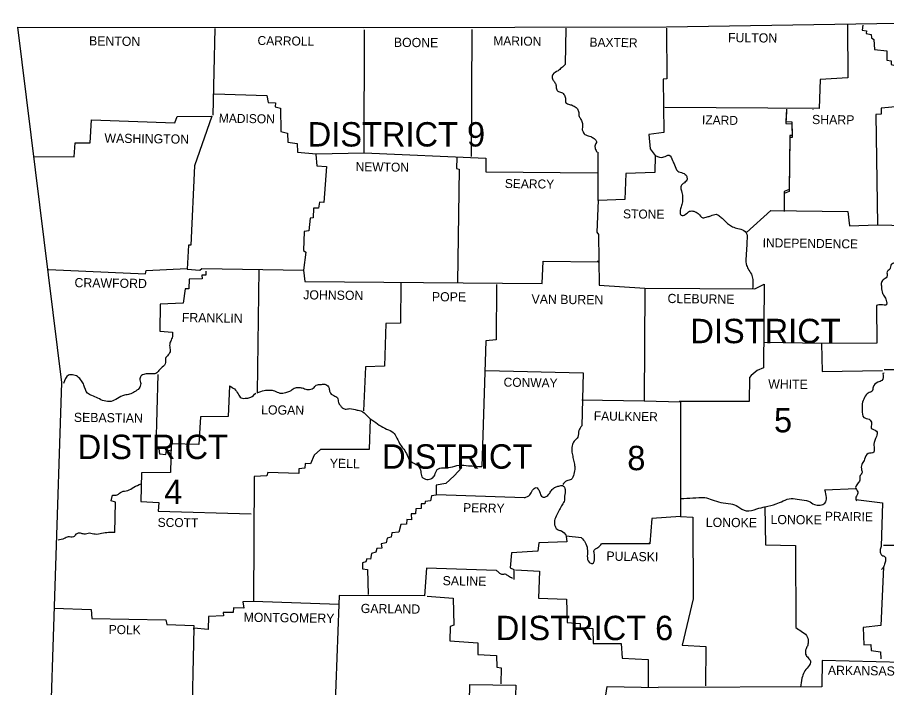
# Model space of a CAD drawing. Extents: x 185 to 5012, y 113 to 2127.
# Drawn here: x 4330.9 to 4728.7, y 1654.2 to 1960.9 of the extents above; entities that cross this region are included whole.
import ezdxf

# ---------------------------------------------------------------- set-up
doc = ezdxf.new("R2010")
doc.units = 0
for name, color, linetype in [('1', 7, 'Continuous'), ('2', 7, 'Continuous'), ('3', 7, 'Continuous')]:
    doc.layers.add(name, color=color, linetype=linetype)

msp = doc.modelspace()

# ---------------------------------------------------------------- linework, layer by layer
at = {"layer": '1'}
msp.add_line((4727.55, 1799.78), (4739.2, 1799.78), dxfattribs=at)
for points in [[(4330.91, 1956.42), (4489.12, 1956.32), (4627.95, 1956.61), (4791.74, 1959.16), (4867.66, 1960.92)], [(4710.82, 1957.49), (4711.02, 1933.23), (4698.3, 1932.55), (4697.91, 1919.24), (4627.17, 1919.63)], [(4717.87, 1957.4), (4717.57, 1955.05), (4719.53, 1954.76), (4719.43, 1953.58), (4721.68, 1953.09), (4721.88, 1951.53), (4722.95, 1950.84), (4723.25, 1946.15), (4728.83, 1945.56), (4728.83, 1941.35), (4730.88, 1941.06), (4730.88, 1939.39), (4732.64, 1938.9), (4732.54, 1933.23), (4734.11, 1932.94), (4734.5, 1920.12), (4726.18, 1919.34), (4726.28, 1916.6), (4723.74, 1916.5), (4724.62, 1866.01), (4764.05, 1865.13), (4764.73, 1786.66), (4739, 1785.98), (4738.51, 1799.19)], [(4330.91, 1956.42), (4351.16, 1793.81), (4342.35, 1528.37)], [(4421.21, 1955.83), (4420.33, 1916.21)], [(4421.02, 1925.89), (4445.09, 1925.11), (4445.67, 1921.98), (4449, 1921.88), (4448.9, 1919.92), (4451.25, 1919.34), (4451.45, 1908.67), (4454.48, 1907.99), (4454.68, 1903.78), (4458.98, 1903.19), (4459.18, 1899.28), (4467.69, 1898.4), (4489.6, 1898.89), (4489.8, 1955.15)], [(4538.82, 1955.34), (4538.52, 1897.22)], [(4581.87, 1956.03), (4581.67, 1939.3)], [(4627.95, 1956.03), (4628.15, 1932.74), (4626.48, 1932.64), (4626.78, 1908.28), (4619.93, 1907.3), (4620.52, 1900.75), (4622.86, 1897.71), (4622.67, 1889.98), (4609.36, 1889.5), (4608.87, 1877.56), (4596.74, 1877.17), (4596.15, 1862.69), (4596.84, 1861.51), (4597.13, 1838.42), (4618.07, 1837.05), (4617.78, 1785.49), (4634.41, 1785), (4634.41, 1732.56), (4621.3, 1731.58), (4620.32, 1720.04), (4598.31, 1719.94)], [(4682.84, 1918.95), (4682.64, 1913.27), (4685.38, 1913.07), (4685.48, 1906.81), (4684.5, 1906.81), (4684.11, 1882.16), (4681.86, 1881.18), (4681.86, 1872.96)], [(4682.84, 1918.06), (4682.64, 1912.39), (4685.38, 1912.19), (4685.48, 1905.93), (4684.5, 1905.93), (4684.11, 1881.28), (4681.86, 1880.3), (4681.86, 1872.08)], [(4695.07, 1918.75), (4695.17, 1918.85)], [(4338.64, 1897.22), (4356.93, 1897.13), (4357.42, 1903.58), (4364.17, 1903.58), (4364.76, 1914.05), (4402.92, 1912.68), (4404.09, 1915.62), (4419.84, 1915.72), (4411.92, 1893.02), (4410.35, 1856.72), (4409.18, 1856.62), (4408.59, 1845.66), (4414.37, 1845.17), (4415.25, 1846.05), (4461.92, 1845.17), (4462.4, 1839.99)], [(4467.49, 1898.2), (4467.88, 1892.92), (4472.38, 1892.63), (4471.21, 1876.19), (4469.16, 1876.29), (4468.76, 1873.65), (4466.42, 1873.65), (4466.32, 1869.14), (4464.85, 1869.05), (4464.36, 1863.27), (4462.21, 1862.98), (4461.92, 1854.17), (4462.89, 1853.49), (4461.92, 1845.17)], [(4489.6, 1898.89), (4545.37, 1896.54), (4545.28, 1890.18), (4596.45, 1889.79)], [(4596.74, 1877.17), (4596.64, 1899.18)], [(4531.97, 1896.83), (4531.87, 1891.75), (4533.14, 1891.45), (4532.36, 1839.79)], [(4664.64, 1862.49), (4675.8, 1872.57), (4711.02, 1872.08), (4711.7, 1865.52), (4724.52, 1866.01)], [(4345.09, 1845.56), (4389.61, 1843.51), (4389.81, 1845.08), (4408.4, 1845.96)], [(4462.4, 1839.99), (4571.01, 1839.11), (4571.5, 1849.38), (4596.74, 1849.09)], [(4596.45, 1849.19), (4596.74, 1849.48)], [(4417.2, 1844.78), (4417.2, 1843.02), (4415.34, 1843.02), (4415.44, 1841.26), (4409.47, 1841.16), (4409.38, 1836.76), (4407.71, 1836.76), (4406.83, 1830.2), (4396.26, 1829.71), (4396.17, 1817.29), (4401.84, 1816.9)], [(4441.37, 1845.56), (4440.68, 1789.11)], [(4506.34, 1839.21), (4506.24, 1820.91), (4499.49, 1820.81), (4498.9, 1801.34), (4490.29, 1801.05), (4489.31, 1780.89)], [(4550.17, 1838.72), (4549.97, 1813.28), (4545.28, 1812.89), (4543.42, 1755.36)], [(4618.07, 1837.05), (4668.36, 1836.76), (4672.66, 1838.81), (4672.37, 1800.56), (4669.44, 1799.29), (4666.79, 1797.04), (4665.91, 1796.16), (4665.82, 1785.2), (4633.82, 1785.2)], [(4724.13, 1829.03), (4724.32, 1811.81), (4698.89, 1811.71), (4672.76, 1812.2)], [(4698.89, 1811.71), (4699.28, 1798.89), (4726.77, 1799.38)], [(4545.08, 1799.29), (4589.79, 1798.21), (4589.21, 1774.04)], [(4395.19, 1797.53), (4394.21, 1763.87), (4395.68, 1763.48), (4395.97, 1761.13), (4398.91, 1760.93), (4399.2, 1762.6), (4401.55, 1762.99)], [(4727.55, 1798.11), (4727.06, 1798.01)], [(4428.06, 1792.24), (4427.38, 1778.25), (4414.66, 1778.15), (4413.97, 1765.43), (4401.35, 1765.73), (4400.96, 1752.62), (4387.75, 1752.52), (4387.36, 1739.41), (4395.68, 1738.92), (4395.38, 1734.91), (4437.85, 1733.73)], [(4764.73, 1786.66), (4766.2, 1733.05), (4742.91, 1732.95), (4742.82, 1730.8), (4736.07, 1730.41), (4735.48, 1719.25), (4727.26, 1719.25)], [(4589.3, 1785.88), (4617.78, 1785.49)], [(4492.34, 1777.27), (4491.95, 1763.18), (4469.65, 1763.09), (4466.71, 1760.54), (4465.05, 1756.63), (4462.6, 1756.82), (4462.5, 1754.57), (4459.67, 1754.28), (4459.76, 1752.22), (4445.58, 1752.62), (4445.09, 1751.05), (4439.22, 1750.86), (4439.02, 1693.62), (4434.13, 1693.52), (4434.52, 1690.59), (4429.82, 1690.68), (4429.73, 1688.53), (4425.13, 1688.53), (4425.23, 1686.97), (4418.38, 1686.77), (4418.28, 1680.8), (4411.63, 1681.39), (4410.55, 1633.25)], [(4534.32, 1754.96), (4530.8, 1751.15), (4526.98, 1747.53), (4522.58, 1746.84), (4522.58, 1742.25), (4520.42, 1741.95), (4520.03, 1739.6), (4517.59, 1739.41), (4517.39, 1738.33), (4515.73, 1738.23), (4515.63, 1736.18), (4513.28, 1736.08), (4513.09, 1733.73), (4511.13, 1733.73), (4511.23, 1730.99), (4509.07, 1731.19), (4508.98, 1729.04), (4506.34, 1728.84), (4505.55, 1725.32), (4502.23, 1725.03), (4501.93, 1723.07), (4500.17, 1722.58), (4499.68, 1720.52), (4497.43, 1720.04), (4497.63, 1717.98), (4495.38, 1717.78), (4494.99, 1716.22), (4492.93, 1715.63), (4492.44, 1712.99), (4490.88, 1713.09), (4490.39, 1711.72), (4488.92, 1711.23), (4488.82, 1708.59), (4491.07, 1708.2), (4491.46, 1696.85)], [(4700.45, 1744.69), (4714.64, 1745.38)], [(4375.52, 1725.22), (4375.82, 1739.02), (4373.86, 1739.6), (4374.45, 1742.25)], [(4562.99, 1741.07), (4522.67, 1742.34)], [(4714.64, 1740.29), (4726.87, 1738.72), (4726.18, 1718.76)], [(4673.06, 1737.06), (4673.25, 1719.55), (4687.05, 1719.25), (4687.14, 1681.68)], [(4634.41, 1732.56), (4640.08, 1732.17), (4640.18, 1694.79), (4635.09, 1673.56), (4645.95, 1673.07), (4645.86, 1655.07)], [(4589.11, 1722.77), (4582.06, 1723.56), (4582.36, 1720.92), (4569.54, 1720.43), (4569.15, 1716.61), (4557.11, 1715.93), (4556.43, 1709.08), (4558.19, 1708.2), (4558.19, 1703.7)], [(4619.83, 1720.13), (4620.32, 1720.62)], [(4550.17, 1707.81), (4518.17, 1708.78), (4517.29, 1696.16), (4478.16, 1696.36), (4477.96, 1692.15)], [(4558.88, 1708.1), (4569.83, 1707.41), (4569.44, 1695.18), (4582.26, 1694.69), (4582.46, 1684.03), (4588.52, 1683.54), (4588.52, 1681.68), (4594.2, 1681.29), (4594.39, 1674.44), (4607.31, 1674.44), (4607.7, 1667.69), (4619.63, 1667.1), (4619.54, 1654.38)], [(4727.26, 1709.37), (4726.09, 1682.56), (4718.06, 1681.68), (4718.26, 1673.76), (4721.49, 1673.85), (4721.58, 1671.11), (4725.99, 1670.63), (4726.09, 1667.4)], [(4518.47, 1695.97), (4530.31, 1695.09), (4530.7, 1682.76), (4529.03, 1682.17), (4528.84, 1675.62), (4541.66, 1674.74), (4541.66, 1669.35), (4550.17, 1668.86), (4550.27, 1663.48), (4552.32, 1663.19), (4552.22, 1655.95)], [(4477.96, 1692.15), (4439.02, 1693.62)], [(4477.96, 1692.15), (4475.71, 1631.2)], [(4347.74, 1690.59), (4364.66, 1690), (4365.05, 1685.89), (4398.91, 1685.2), (4399.3, 1683.05), (4411.63, 1682.66), (4411.53, 1680.8)], [(4736.26, 1665.64), (4699.28, 1666.61), (4699.08, 1654.58), (4624.23, 1654.29)], [(4476.4, 1639.32), (4532.36, 1638.53), (4533.44, 1647.83), (4537.84, 1647.83), (4537.94, 1655.66), (4559.07, 1655.36), (4558.88, 1650.67), (4564.35, 1650.27), (4564.35, 1641.66), (4567.88, 1641.37)], [(4567.88, 1641.37), (4573.36, 1642.15), (4573.75, 1645.48), (4576.98, 1646.07), (4577.17, 1648.02), (4599.97, 1648.71), (4600.85, 1654.68), (4624.23, 1654.29)]]:
    msp.add_lwpolyline(points, dxfattribs=at)
for points in [[(4581.67, 1939.3), (4579.91, 1937.83), (4578.35, 1936.46), (4576, 1934.8), (4575.7, 1933.23), (4576.49, 1931.66), (4577.27, 1930.39), (4577.56, 1928.63), (4578.25, 1927.16), (4579.91, 1926.58), (4581.28, 1925.31), (4581.77, 1923.54), (4581.97, 1921.88), (4583.53, 1921.1), (4585.29, 1920.51), (4586.96, 1919.34), (4587.74, 1917.87), (4587.93, 1916.01), (4588.62, 1914.54), (4589.4, 1912.78), (4589.6, 1911.31), (4589.4, 1909.85), (4589.79, 1908.48), (4591.07, 1907.11), (4593.32, 1906.42), (4594.88, 1905.44), (4595.96, 1904.07), (4595.27, 1902.41), (4595.37, 1900.94), (4596.25, 1899.18)], [(4622.86, 1897.71), (4626.78, 1897.03), (4629.13, 1897.91), (4630.79, 1895.37), (4631.67, 1893.41), (4633.14, 1890.57), (4635.49, 1889.69), (4637.25, 1888.13), (4637.25, 1886.46), (4635.68, 1884.9), (4634.51, 1883.33), (4634.9, 1881.47), (4635.29, 1878.93), (4635.29, 1876.48), (4634.7, 1874.23), (4634.21, 1872.18), (4634.7, 1870.42), (4636.56, 1870.71), (4638.52, 1872.18), (4640.57, 1872.18), (4642.53, 1871.1), (4644.58, 1869.24), (4646.64, 1869.63), (4648.3, 1870.12), (4650.65, 1870.81), (4652.31, 1869.93), (4653.78, 1868.75), (4655.54, 1866.89), (4657.21, 1865.72), (4659.36, 1864.64), (4662, 1863.96), (4664.45, 1862.3), (4664.84, 1859.46), (4664.74, 1857.01), (4664.54, 1853.98), (4664.35, 1850.65), (4664.64, 1847.42), (4665.72, 1845.27), (4667.09, 1842.73), (4667.48, 1840.38), (4667.38, 1836.66)], [(4741.64, 1864.25), (4740.47, 1861.22), (4739.1, 1858.28), (4738.22, 1855.74), (4736.36, 1854.27), (4735.77, 1852.9), (4734.11, 1852.32), (4732.84, 1850.36), (4732.25, 1848.6), (4730.88, 1847.82), (4730.19, 1845.66), (4728.92, 1844.49), (4729.02, 1842.53), (4727.55, 1841.16), (4726.38, 1839.6), (4726.38, 1837.44), (4726.87, 1834.61), (4727.85, 1832.94), (4728.73, 1830.79), (4728.63, 1829.42), (4726.18, 1829.42), (4724.13, 1829.03)], [(4401.84, 1816.9), (4401.84, 1814.84), (4401.06, 1812.69), (4400.57, 1810.83), (4400.86, 1808.39), (4399.98, 1806.43), (4398.71, 1804.86), (4398.71, 1802.91), (4397.24, 1800.85), (4395.68, 1799.29), (4394.31, 1798.01), (4391.86, 1797.82), (4389.81, 1797.72), (4387.75, 1797.04), (4386.97, 1795.57), (4387.36, 1793.32), (4386.58, 1791.17), (4384.52, 1789.5), (4382.27, 1788.43), (4379.93, 1788.03), (4376.7, 1786.47), (4373.76, 1785.2), (4370.63, 1785.39), (4367.7, 1786.66), (4365.05, 1787.84), (4363, 1789.01), (4361.34, 1792.63), (4360.26, 1794.59), (4358.4, 1796.55), (4356.15, 1797.33), (4354.29, 1797.13), (4352.04, 1793.32)], [(4727.06, 1798.01), (4726.57, 1794.79), (4724.72, 1793.91), (4722.56, 1791.75), (4722.07, 1789.8), (4720.31, 1789.01), (4718.65, 1786.96), (4717.57, 1784.12), (4717.57, 1781.19), (4718.26, 1777.86), (4720.7, 1776.98), (4721.88, 1775.02), (4721.68, 1772.97), (4724.03, 1771.6), (4724.42, 1770.42), (4724.03, 1769.15), (4722.95, 1765.53), (4723.05, 1763.09), (4722.86, 1762.01), (4720.22, 1761.32), (4718.65, 1758.68), (4717.57, 1756.82), (4717.18, 1754.38), (4717.48, 1752.62), (4716.69, 1751.25), (4716.4, 1749.19), (4715.42, 1747.43), (4714.54, 1745.77), (4715.52, 1743.81), (4715.23, 1742.44), (4714.64, 1740.29), (4715.13, 1739.6)], [(4428.06, 1792.24), (4430.22, 1790.87), (4431.88, 1788.62), (4433.35, 1786.76), (4435.79, 1786.66), (4437.75, 1787.06), (4440, 1789.01)], [(4440.68, 1789.11), (4443.91, 1790.19), (4446.26, 1790.38), (4448.61, 1789.99), (4451.06, 1789.01), (4453.7, 1789.21), (4455.65, 1789.89), (4457.61, 1791.17), (4459.76, 1791.56), (4461.82, 1791.17), (4463.97, 1790.58), (4466.32, 1791.26), (4467.69, 1792.54), (4470.04, 1792.93), (4472.09, 1792.93), (4473.56, 1791.26), (4473.85, 1789.5), (4475.71, 1787.84), (4477.37, 1786.76), (4477.86, 1784.71), (4478.74, 1783.24), (4479.62, 1782.26), (4480.9, 1781.67), (4483.05, 1781.87), (4486.38, 1781.19), (4488.53, 1780.7), (4490.49, 1779.03), (4492.34, 1777.27)], [(4492.34, 1777.27), (4495.77, 1774.92), (4499, 1772.87), (4502.32, 1771.4), (4504.18, 1769.25), (4505.85, 1765.92), (4507.22, 1763.87), (4508.98, 1761.32), (4510.25, 1758.49), (4512.3, 1756.92), (4514.46, 1755.55), (4515.53, 1753.11), (4516.02, 1750.66), (4518.37, 1749.49), (4520.62, 1749.97), (4521.89, 1751.44), (4523.07, 1753.99), (4525.71, 1754.77), (4529.13, 1755.06), (4533.05, 1755.94), (4537.35, 1755.75), (4543.42, 1755.36)], [(4589.21, 1774.04), (4587.93, 1771.79), (4587.35, 1768.86), (4585.78, 1767), (4584.8, 1764.85), (4584.71, 1762.01), (4585.19, 1759.47), (4585.68, 1757.02), (4586.08, 1754.77), (4585.59, 1751.93), (4584.31, 1749.49), (4582.36, 1748.8), (4580.5, 1747.14)], [(4374.45, 1742.25), (4376.6, 1742.44), (4378.65, 1743.81), (4381.39, 1744.4), (4384.13, 1745.87), (4387.56, 1747.43)], [(4562.99, 1741.07), (4565.43, 1742.44), (4566.7, 1744.5), (4568.27, 1745.77), (4569.83, 1744.01), (4571.2, 1741.46), (4572.67, 1741.46), (4574.53, 1743.22), (4575.7, 1744.79), (4577.17, 1745.96), (4578.74, 1746.45), (4580.4, 1746.65), (4581.67, 1744.79), (4581.28, 1741.85), (4581.28, 1739.9), (4580.21, 1737.84), (4579.03, 1735.69), (4577.76, 1733.24), (4576.78, 1730.6), (4576.98, 1728.06), (4578.35, 1726.39), (4579.91, 1725.91), (4582.06, 1723.75)], [(4634.6, 1740.78), (4640.08, 1740.97), (4645.46, 1741.17), (4648.89, 1740.19), (4652.8, 1738.92), (4657.4, 1738.33), (4660.63, 1737.06), (4664.45, 1735.1), (4669.34, 1735.98), (4673.15, 1736.96), (4678.14, 1738.23), (4681.37, 1739.6), (4685.09, 1740.78), (4688.81, 1740.29), (4693.02, 1739.51), (4695.66, 1737.94), (4700.45, 1738.63), (4700.45, 1744.69)], [(4375.52, 1725.22), (4372.68, 1725.12), (4369.46, 1724.73), (4366.52, 1724.34), (4363.88, 1724.83), (4361.43, 1724.44), (4359.77, 1724.83), (4357.72, 1724.34), (4356.54, 1723.17), (4354.1, 1723.17), (4352.33, 1722.38), (4349.5, 1721.7)], [(4589.11, 1722.77), (4590.77, 1720.62), (4591.75, 1717.69), (4591.75, 1714.36), (4592.53, 1711.62), (4594.1, 1711.03), (4595.08, 1713.38), (4594.88, 1715.73), (4594.88, 1717.1), (4596.54, 1718.27), (4598.31, 1719.94)], [(4726.18, 1718.76), (4725.79, 1716.81), (4726.57, 1714.75), (4727.94, 1714.07), (4728.14, 1712.11), (4727.65, 1710.15), (4727.26, 1709.37), (4726.38, 1708.2)], [(4557.51, 1704.19), (4555.65, 1705.16), (4554.18, 1706.04), (4552.61, 1705.95), (4551.34, 1706.73), (4550.17, 1707.81)], [(4687.14, 1681.68), (4689.59, 1680.02), (4692.13, 1678.06), (4692.82, 1675.42), (4692.62, 1673.56), (4691.84, 1672), (4691.65, 1669.55), (4692.82, 1667.79), (4693.9, 1666.32), (4692.82, 1663.68), (4690.96, 1661.23), (4689.98, 1658.49), (4689.3, 1654.38)]]:
    msp.add_spline(points, degree=3, dxfattribs=at)

# ---------------------------------------------------------------- texts
at = {"layer": '2'}
for s, height, rotation, p in [('FULTON', 4.206, 359.4996, (4656.13, 1949.57)), ('BENTON', 4.207, 359.2527, (4363.68, 1948.1)), ('CARROLL', 4.109, 359.1481, (4440.78, 1948.3)), ('BOONE', 4.207, 359.4001, (4503.2, 1947.42)), ('MARION', 4.109, 359.1854, (4548.7, 1948.2)), ('BAXTER', 4.109, 359.2559, (4592.73, 1947.51)), ('MADISON', 4.109, 359.0906, (4423.07, 1912.78)), ('IZARD', 4.108, 358.9258, (4644.19, 1912)), ('SHARP', 4.206, 359.3905, (4694.58, 1912.1)), ('WASHINGTON', 4.206, 359.232, (4370.73, 1903.58)), ('NEWTON', 4.109, 359.2717, (4485.69, 1890.57)), ('SEARCY', 4.108, 359.2527, (4553.98, 1882.84)), ('STONE', 4.108, 359.4001, (4608.09, 1868.95)), ('INDEPENDENCE', 4.1081, 359.2187, (4671.98, 1855.74)), ('CRAWFORD', 4.206, 359.2771, (4357.03, 1837.44)), ('JOHNSON', 4.207, 359.3514, (4461.72, 1831.87)), ('POPE', 4.207, 359.6155, (4520.62, 1830.99)), ('VAN BUREN', 4.207, 359.3508, (4566.21, 1829.91)), ('CLEBURNE', 4.206, 359.2535, (4628.44, 1830.2)), ('FRANKLIN', 4.207, 359.1815, (4406.15, 1821.5)), ('CONWAY', 4.108, 359.0371, (4553.4, 1791.95)), ('WHITE', 4.207, 359.3139, (4674.52, 1791.07)), ('LOGAN', 4.207, 359.3969, (4442.45, 1779.23)), ('SEBASTIAN', 4.206, 359.2816, (4356.74, 1775.8)), ('FAULKNER', 4.109, 359.2486, (4594.69, 1776.49)), ('YELL', 4.207, 359.1987, (4473.85, 1754.77)), ('PERRY', 4.109, 359.0858, (4534.9, 1734.52)), ('PRAIRIE', 4.109, 359.2116, (4700.45, 1730.6)), ('SCOTT', 4.109, 359.4063, (4395.09, 1727.76)), ('LONOKE', 4.207, 359.4974, (4645.95, 1727.76)), ('LONOKE', 4.207, 359.4974, (4675.6, 1729.04)), ('PULASKI', 4.207, 359.053, (4600.46, 1712.31)), ('SALINE', 4.207, 359.1491, (4525.51, 1701.05)), ('GARLAND', 4.207, 359.3658, (4488.04, 1688.33)), ('MONTGOMERY', 4.207, 359.2944, (4434.42, 1684.32)), ('POLK', 4.108, 359.2152, (4372.68, 1678.75)), ('ARKANSAS', 4.206, 359.2678, (4701.82, 1660.06))]:
    msp.add_text(s, height=height, rotation=rotation, dxfattribs=at).set_placement(p)
at = {"layer": '3'}
for s, height, p in [('DISTRICT 9', 11.154, (4463.77, 1901.82)), ('DISTRICT', 11.154, (4638.91, 1811.81)), ('5', 11.15, (4677.17, 1771.01)), ('DISTRICT', 11.154, (4358.5, 1758.78)), ('DISTRICT', 11.154, (4497.82, 1754.38)), ('8', 11.15, (4610.05, 1753.69)), ('4', 11.15, (4398.12, 1738.23)), ('DISTRICT 6', 11.154, (4549.87, 1675.91))]:
    msp.add_text(s, height=height, dxfattribs=at).set_placement(p)

doc.saveas('drawing.dxf')
